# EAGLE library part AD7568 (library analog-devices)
LC2MOS Octal 12-Bit DAC Source: http://www.analog.com/UploadedFiles/Data_Sheets/843987253ad7568.pdf
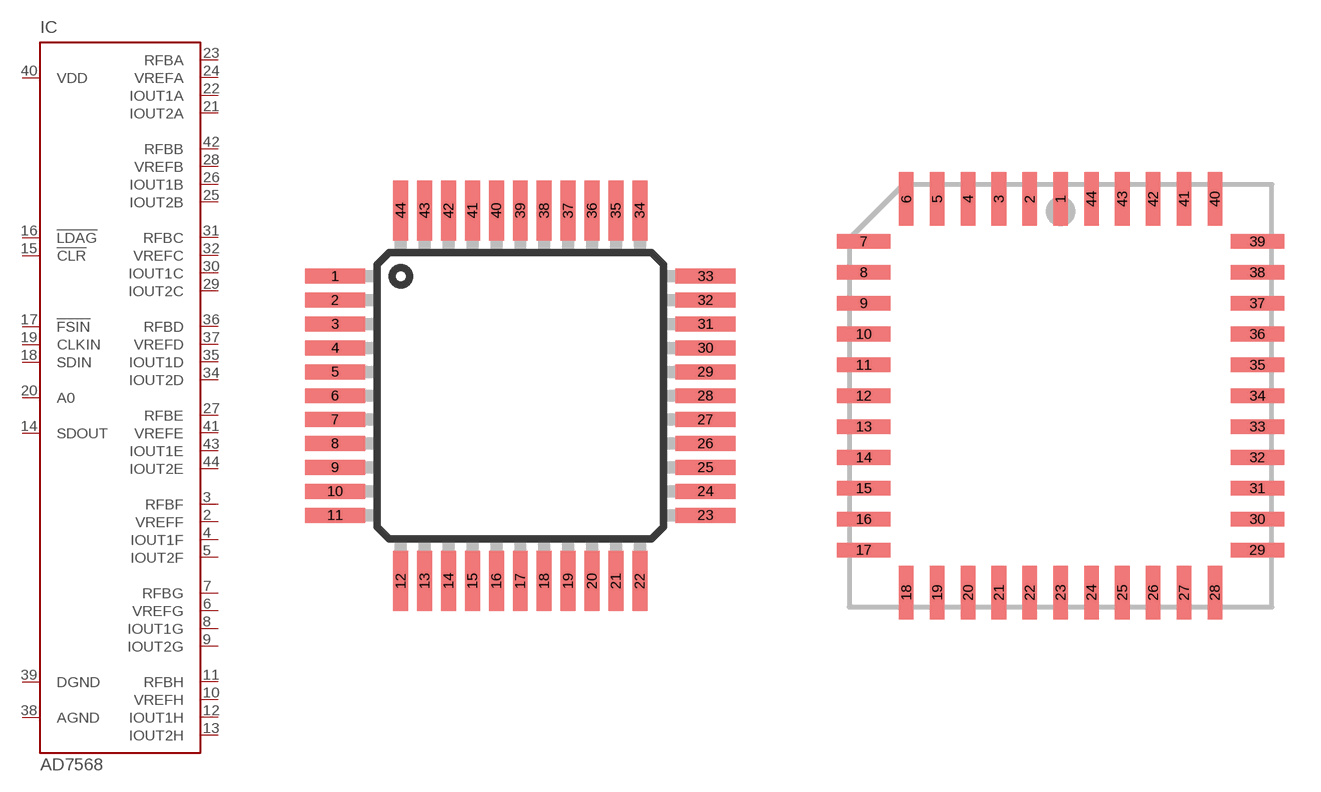
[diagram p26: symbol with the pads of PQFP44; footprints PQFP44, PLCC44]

Designator prefix IC

## AD7568S (MF: ALTERA CORPORATION; MPN: AD7568BSZ; OC_FARNELL: 1311330; OC_NEWARK: 59K5056)  [PQFP44]
2  VREFF  pas
3  RFBF  pas
4  IOUT1F  pas
5  IOUT2F  pas
6  VREFG  pas
7  RFBG  pas
8  IOUT1G  pas
9  IOUT2G  pas
10  VREFH  pas
11  RFBH  pas
12  IOUT1H  pas
13  IOUT2H  pas
14  SDOUT  in
15  !CLR  in
16  !LDAG  in
17  !FSIN  in
18  SDIN  in
19  CLKIN  in
20  A0  in
21  IOUT2A  pas
22  IOUT1A  pas
23  RFBA  pas
24  VREFA  pas
25  IOUT2B  pas
26  IOUT1B  pas
27  RFBE  pas
28  VREFB  pas
29  IOUT2C  pas
30  IOUT1C  pas
31  RFBC  pas
32  VREFC  pas
34  IOUT2D  pas
35  IOUT1D  pas
36  RFBD  pas
37  VREFD  pas
38  AGND  pwr
39  DGND  pwr
40  VDD  pwr
41  VREFE  pas
42  RFBB  pas
43  IOUT1E  pas
44  IOUT2E  pas

## AD7568P (MPN: AD7568BP; OC_FARNELL: unknown; OC_NEWARK: 09B5836)  [PLCC44]
1  DGND  pwr
2  VDD  pwr
3  VREFE  pas
4  RFBE  pas
5  IOUT1E  pas
6  IOUT2E  pas
8  VREFF  pas
9  RFBF  pas
10  IOUT1F  pas
11  IOUT2F  pas
12  VREFG  pas
13  RFBG  pas
14  IOUT1G  pas
15  IOUT2G  pas
16  VREFH  pas
17  RFBH  pas
18  IOUT1H  pas
19  IOUT2H  pas
20  SDOUT  in
21  !CLR  in
22  !LDAG  in
23  !FSIN  in
24  SDIN  in
25  CLKIN  in
26  A0  in
27  IOUT2A  pas
28  IOUT1A  pas
29  RFBA  pas
30  VREFA  pas
31  IOUT2B  pas
32  IOUT1B  pas
33  RFBB  pas
34  VREFB  pas
35  IOUT2C  pas
36  IOUT1C  pas
37  RFBC  pas
38  VREFC  pas
40  IOUT2D  pas
41  IOUT1D  pas
42  RFBD  pas
43  VREFD  pas
44  AGND  pwr

## Footprint PQFP44 (pad centres in mm)
Plastic Quad Flat Package
smd 2 x 0.5: 1 -6.2,4; 2 -6.2,3.2; 3 -6.2,2.4; 4 -6.2,1.6; 5 -6.2,0.8; 6 -6.2,0; 7 -6.2,-0.8; 8 -6.2,-1.6; 9 -6.2,-2.4; 10 -6.2,-3.2; 11 -6.2,-4; 23 6.2,-4; 24 6.2,-3.2; 25 6.2,-2.4; 26 6.2,-1.6; 27 6.2,-0.8; 28 6.2,0; 29 6.2,0.8; 30 6.2,1.6; 31 6.2,2.4; 32 6.2,3.2; 33 6.2,4
smd 0.5 x 2: 12 -4,-6.2; 13 -3.2,-6.2; 14 -2.4,-6.2; 15 -1.6,-6.2; 16 -0.8,-6.2; 17 0,-6.2; 18 0.8,-6.2; 19 1.6,-6.2; 20 2.4,-6.2; 21 3.2,-6.2; 22 4,-6.2; 34 4,6.2; 35 3.2,6.2; 36 2.4,6.2; 37 1.6,6.2; 38 0.8,6.2; 39 0,6.2; 40 -0.8,6.2; 41 -1.6,6.2; 42 -2.4,6.2; 43 -3.2,6.2; 44 -4,6.2

## Footprint PLCC44 (pad centres in mm)
PLASTIC LEADED CHIP CARRIER square
smd 0.6 x 2.2: 1 0,8.1; 2 -1.27,8.1; 3 -2.54,8.1; 4 -3.81,8.1; 5 -5.08,8.1; 6 -6.35,8.1; 18 -6.35,-8.1; 19 -5.08,-8.1; 20 -3.81,-8.1; 21 -2.54,-8.1; 22 -1.27,-8.1; 23 0,-8.1; 24 1.27,-8.1; 25 2.54,-8.1; 26 3.81,-8.1; 27 5.08,-8.1; 28 6.35,-8.1; 40 6.35,8.1; 41 5.08,8.1; 42 3.81,8.1; 43 2.54,8.1; 44 1.27,8.1
smd 2.2 x 0.6: 7 -8.1,6.35; 8 -8.1,5.08; 9 -8.1,3.81; 10 -8.1,2.54; 11 -8.1,1.27; 12 -8.1,0; 13 -8.1,-1.27; 14 -8.1,-2.54; 15 -8.1,-3.81; 16 -8.1,-5.08; 17 -8.1,-6.35; 29 8.1,-6.35; 30 8.1,-5.08; 31 8.1,-3.81; 32 8.1,-2.54; 33 8.1,-1.27; 34 8.1,0; 35 8.1,1.27; 36 8.1,2.54; 37 8.1,3.81; 38 8.1,5.08; 39 8.1,6.35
